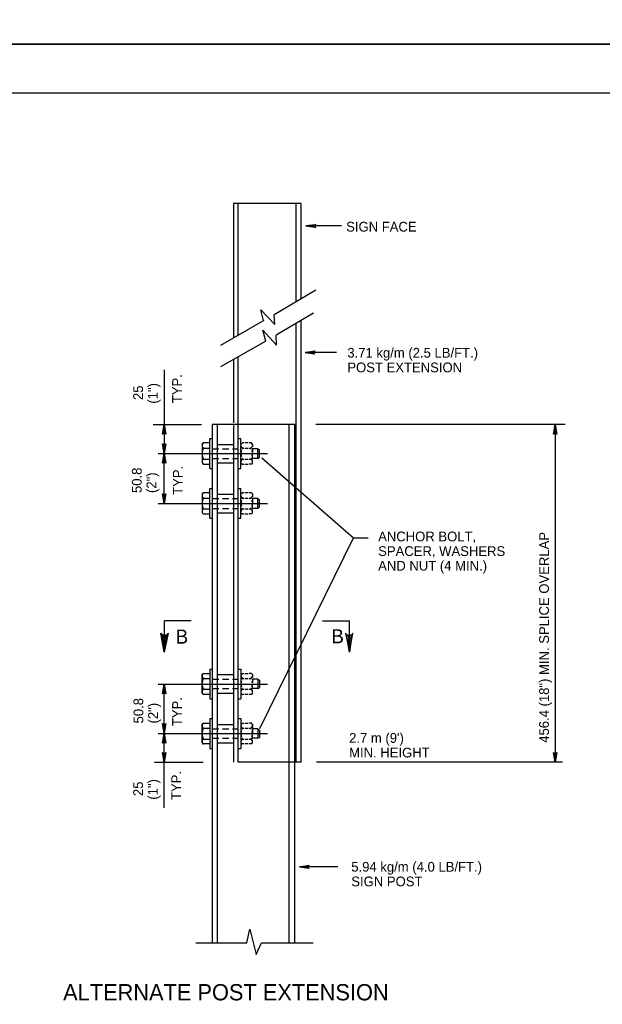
# Model space of a CAD drawing. Extents: x 644358 to 648627, y 294594 to 295782.
# Drawn here: x 644576.7 to 644755.6, y 294892.7 to 295195.1 of the extents above; entities that cross this region are included whole.
import ezdxf

# ---------------------------------------------------------------- set-up
doc = ezdxf.new("R2010")
doc.units = 0
for name, color, linetype in [('1', 7, 'Continuous'), ('2', 7, 'Continuous'), ('3', 7, 'Continuous'), ('4', 7, 'Continuous'), ('PLT-BNDY', 7, 'Continuous')]:
    doc.layers.add(name, color=color, linetype=linetype)

# ---------------------------------------------------------------- blocks, each defined once
blk = doc.blocks.new('RARROW')
at = {"layer": '3'}
blk.add_lwpolyline([(-2.2695, 0.285), (-2.184875, 0.12075), (0, 0), (-2.2695, 0.285), (-2.38575, 0.384625), (0, 0), (-2.183125, -0.108), (-2.262875, -0.2705), (0, 0), (-2.38575, -0.379125), (-2.262875, -0.2705)], dxfattribs=at)

msp = doc.modelspace()

# ---------------------------------------------------------------- linework, layer by layer
at = {"layer": '1'}
for p, q in [((644398.31, 295172.63), (645184.31, 295172.63)), ((644648.21, 295064.63), (644648.21, 295063.88)), ((644648.21, 295063.51), (644648.21, 295062.13)), ((644648.21, 295060.26), (644648.21, 295061.51)), ((644648.21, 295059.01), (644648.21, 295060.01)), ((644648.21, 295049.51), (644648.21, 295048.51)), ((644648.21, 295048.13), (644648.21, 295046.76)), ((644648.21, 295045.01), (644648.21, 295046.26)), ((644648.21, 295043.63), (644648.21, 295044.63)), ((644648.21, 294994.01), (644648.21, 294993.01)), ((644648.21, 294992.63), (644648.21, 294991.38)), ((644648.21, 294989.51), (644648.21, 294990.88)), ((644648.21, 294988.26), (644648.21, 294989.13)), ((644648.21, 294978.63), (644648.21, 294977.63)), ((644648.21, 294977.38), (644648.21, 294976.01)), ((644648.21, 294974.13), (644648.21, 294975.51)), ((644648.21, 294973.01), (644648.21, 294973.76))]:
    msp.add_line(p, q, dxfattribs=at)
for points in [[(644622.09, 295006.26), (644621.46, 295006.01), (644621.09, 295000.88), (644622.09, 295006.26), (644622.34, 295006.63), (644621.09, 295000.88), (644620.96, 295006.01), (644620.46, 295006.26), (644621.09, 295000.88), (644620.09, 295006.63), (644620.46, 295006.26)], [(644677.09, 295006.26), (644677.59, 295006.01), (644677.96, 295000.88), (644677.09, 295006.26), (644676.71, 295006.63), (644677.96, 295000.88), (644678.21, 295006.01), (644678.71, 295006.26), (644677.96, 295000.88), (644678.96, 295006.63), (644678.71, 295006.26)]]:
    msp.add_lwpolyline(points, dxfattribs=at)
for centre, radius, start, end in [((644645.47, 295064.34), 0.81, 184.8919, 254.2247), ((644647.69, 295061.85), 3.04, 146.6027, 154.678), ((644647.35, 295064.34), 0.81, 285.7753, 351.6558), ((644645.13, 295061.85), 3.04, 24.9174, 33.3973), ((644647.69, 295061.85), 3.04, 162.8799, 197.6126), ((644645.47, 295059.39), 0.81, 106.5107, 186.623), ((644647.69, 295061.85), 3.04, 205.6812, 213.3973), ((644647.35, 295059.39), 0.81, 358.7185, 73.4893), ((644645.13, 295061.85), 3.04, 326.6027, 334.9746), ((644645.13, 295061.85), 3.04, 6.0459, 16.9125), ((644645.13, 295061.85), 3.04, 344.0189, 354.4846), ((644645.47, 295049.01), 0.81, 184.8919, 254.2247), ((644647.69, 295046.52), 3.04, 146.6027, 154.678), ((644647.35, 295049.01), 0.81, 285.7753, 351.6558), ((644645.13, 295046.52), 3.04, 24.9174, 33.3973), ((644647.69, 295046.52), 3.04, 162.8799, 197.6126), ((644645.47, 295044.05), 0.81, 106.5107, 186.623), ((644647.69, 295046.52), 3.04, 205.6812, 213.3973), ((644647.35, 295044.05), 0.81, 358.7185, 73.4893), ((644645.13, 295046.52), 3.04, 326.6027, 334.9746), ((644645.13, 295046.52), 3.04, 6.0459, 16.9125), ((644645.13, 295046.52), 3.04, 344.0189, 354.4846), ((644645.47, 294993.59), 0.81, 173.377, 253.4893), ((644647.35, 294993.59), 0.81, 286.5107, 1.2815), ((644647.69, 294991.13), 3.04, 162.3874, 197.1201), ((644647.69, 294991.13), 3.04, 146.6027, 154.3188), ((644645.13, 294991.13), 3.04, 25.0254, 33.3973), ((644645.13, 294991.13), 3.04, 343.0875, 353.9541), ((644645.13, 294991.13), 3.04, 5.5154, 15.9811), ((644645.47, 294988.64), 0.81, 105.7753, 175.1081), ((644647.69, 294991.13), 3.04, 205.322, 213.3973), ((644647.35, 294988.64), 0.81, 8.3442, 74.2247), ((644645.13, 294991.13), 3.04, 326.6027, 335.0826), ((644645.47, 294978.26), 0.81, 173.377, 253.4893), ((644647.35, 294978.26), 0.81, 286.5107, 1.2815), ((644647.69, 294975.8), 3.04, 162.3874, 197.1201), ((644647.69, 294975.8), 3.04, 146.6027, 154.3188), ((644645.13, 294975.8), 3.04, 25.0254, 33.3973), ((644645.13, 294975.8), 3.04, 343.0875, 353.9541), ((644645.13, 294975.8), 3.04, 5.5154, 15.9811), ((644645.47, 294973.3), 0.81, 105.7753, 175.1081), ((644647.69, 294975.8), 3.04, 205.322, 213.3973), ((644647.35, 294973.3), 0.81, 8.3442, 74.2247), ((644645.13, 294975.8), 3.04, 326.6027, 335.0826)]:
    msp.add_arc(centre, radius, start, end, dxfattribs=at)
for centre, major_axis, start_param, end_param in [((644635.44, 295061.85), (0, -3.04), 4.129496, 5.295282), ((644633.44, 295064.34), (0, 0.81), 0.448108, 2.866262), ((644633.44, 295059.39), (0, -0.81), 3.429758, 5.835077), ((644635.44, 295046.52), (0, -3.04), 4.129496, 5.295282), ((644633.44, 295049.01), (0, 0.81), 0.448108, 2.866262), ((644633.44, 295044.05), (0, -0.81), 3.429758, 5.835077), ((644633.44, 294993.59), (0, 0.81), 0.448108, 2.853427), ((644635.44, 294991.13), (0, 3.04), 0.987904, 2.153689), ((644633.44, 294988.64), (0, -0.81), 3.416923, 5.835077), ((644633.44, 294978.26), (0, 0.81), 0.448108, 2.853427), ((644635.44, 294975.8), (0, 3.04), 0.987904, 2.153689), ((644633.44, 294973.3), (0, -0.81), 3.416923, 5.835077)]:
    msp.add_ellipse(centre, major_axis=major_axis, ratio=0.9, start_param=start_param, end_param=end_param, dxfattribs=at)
at = {"layer": '2'}
for p, q in [((644663.09, 295138.63), (644642.34, 295138.63)), ((644642.34, 295138.63), (644642.34, 295097.38)), ((644643.84, 295098.26), (644643.84, 295138.63)), ((644661.59, 295108.38), (644661.59, 295138.88)), ((644663.09, 295109.38), (644663.09, 295138.63)), ((644667.59, 295112.01), (644654.84, 295104.51)), ((644651.71, 295102.76), (644638.34, 295095.01)), ((644666.96, 295105.01), (644655.46, 295098.26)), ((644663.09, 294967.01), (644663.09, 295102.76)), ((644661.59, 294967.01), (644661.59, 295101.88)), ((644652.34, 295096.38), (644638.34, 295088.51)), ((644642.34, 295090.76), (644642.34, 295071.26)), ((644643.84, 294967.01), (644643.84, 295091.51)), ((644661.21, 295070.76), (644635.84, 295070.76)), ((644635.84, 295070.76), (644635.84, 294911.51)), ((644637.34, 295070.76), (644637.34, 294911.51)), ((644642.34, 295070.51), (644642.34, 294967.01)), ((644659.46, 294911.51), (644659.46, 295070.76)), ((644661.21, 294911.51), (644661.21, 295070.76)), ((644635.09, 295066.51), (644635.84, 295066.51)), ((644635.09, 295057.26), (644635.09, 295066.51)), ((644643.84, 295066.51), (644644.59, 295066.51)), ((644644.59, 295057.26), (644644.59, 295066.51)), ((644632.71, 295064.63), (644633.09, 295065.13)), ((644632.71, 295064.63), (644632.71, 295059.01)), ((644635.09, 295065.13), (644633.09, 295065.13)), ((644633.21, 295063.51), (644635.09, 295063.51)), ((644635.84, 295063.26), (644637.84, 295063.26)), ((644637.34, 295064.63), (644642.34, 295064.63)), ((644638.96, 295063.26), (644640.96, 295063.26)), ((644642.09, 295063.26), (644643.84, 295063.26)), ((644644.59, 295064.63), (644645.09, 295065.13)), ((644645.59, 295065.13), (644645.09, 295065.13)), ((644645.21, 295063.51), (644645.59, 295063.51)), ((644646.84, 295065.13), (644645.96, 295065.13)), ((644645.96, 295063.51), (644646.84, 295063.51)), ((644647.84, 295065.13), (644647.21, 295065.13)), ((644647.21, 295063.51), (644647.71, 295063.51)), ((644648.21, 295064.63), (644647.84, 295065.13)), ((644649.84, 295063.26), (644648.21, 295063.26)), ((644649.84, 295060.38), (644649.84, 295063.26)), ((644649.84, 295063.26), (644650.34, 295063.01)), ((644650.34, 295060.76), (644650.34, 295063.01)), ((644633.21, 295060.13), (644635.09, 295060.13)), ((644635.84, 295060.38), (644637.84, 295060.38)), ((644638.96, 295060.38), (644640.96, 295060.38)), ((644642.09, 295060.38), (644643.84, 295060.38)), ((644645.21, 295060.13), (644645.59, 295060.13)), ((644645.96, 295060.13), (644646.84, 295060.13)), ((644647.21, 295060.13), (644647.71, 295060.13)), ((644649.84, 295060.38), (644648.21, 295060.38)), ((644649.84, 295060.38), (644650.34, 295060.76)), ((644632.71, 295059.01), (644633.09, 295058.63)), ((644633.09, 295058.63), (644635.09, 295058.63)), ((644635.09, 295057.26), (644635.84, 295057.26)), ((644637.34, 295059.01), (644642.34, 295059.01)), ((644643.84, 295057.26), (644644.59, 295057.26)), ((644644.59, 295059.01), (644645.09, 295058.63)), ((644645.09, 295058.63), (644645.59, 295058.63)), ((644645.96, 295058.63), (644646.84, 295058.63)), ((644647.84, 295058.63), (644647.21, 295058.63)), ((644648.21, 295059.01), (644647.84, 295058.63)), ((644635.09, 295051.13), (644635.84, 295051.13)), ((644635.09, 295042.01), (644635.09, 295051.13)), ((644643.84, 295051.13), (644644.59, 295051.13)), ((644644.59, 295042.01), (644644.59, 295051.13)), ((644632.71, 295049.51), (644633.09, 295049.76)), ((644632.71, 295049.51), (644632.71, 295043.63)), ((644635.09, 295049.76), (644633.09, 295049.76)), ((644633.21, 295048.13), (644635.09, 295048.13)), ((644635.84, 295048.01), (644637.84, 295048.01)), ((644637.34, 295049.38), (644642.34, 295049.38)), ((644638.96, 295048.01), (644640.96, 295048.01)), ((644642.09, 295048.01), (644643.84, 295048.01)), ((644644.59, 295049.51), (644645.09, 295049.76)), ((644645.59, 295049.76), (644645.09, 295049.76)), ((644645.21, 295048.13), (644645.59, 295048.13)), ((644646.84, 295049.76), (644645.96, 295049.76)), ((644645.96, 295048.13), (644646.84, 295048.13)), ((644647.84, 295049.76), (644647.21, 295049.76)), ((644647.21, 295048.13), (644647.71, 295048.13)), ((644648.21, 295049.51), (644647.84, 295049.76)), ((644649.84, 295048.01), (644648.21, 295048.01)), ((644649.84, 295045.01), (644649.84, 295048.01)), ((644649.84, 295048.01), (644650.34, 295047.63)), ((644633.21, 295044.88), (644635.09, 295044.88)), ((644635.84, 295045.01), (644637.84, 295045.01)), ((644638.96, 295045.01), (644640.96, 295045.01)), ((644642.09, 295045.01), (644643.84, 295045.01)), ((644645.21, 295044.88), (644645.59, 295044.88)), ((644645.96, 295044.88), (644646.84, 295044.88)), ((644647.21, 295044.88), (644647.71, 295044.88)), ((644649.84, 295045.01), (644648.21, 295045.01)), ((644649.84, 295045.01), (644650.34, 295045.51)), ((644650.34, 295045.51), (644650.34, 295047.63)), ((644632.71, 295043.63), (644633.09, 295043.38)), ((644633.09, 295043.38), (644635.09, 295043.38)), ((644635.09, 295042.01), (644635.84, 295042.01)), ((644637.34, 295043.63), (644642.34, 295043.63)), ((644643.84, 295042.01), (644644.59, 295042.01)), ((644644.59, 295043.63), (644645.09, 295043.38)), ((644645.09, 295043.38), (644645.59, 295043.38)), ((644645.96, 295043.38), (644646.84, 295043.38)), ((644647.84, 295043.38), (644647.21, 295043.38)), ((644648.21, 295043.63), (644647.84, 295043.38)), ((644629.34, 295010.51), (644621.21, 295010.51)), ((644621.21, 295003.76), (644621.21, 295010.51)), ((644669.71, 295010.51), (644677.96, 295010.51)), ((644677.96, 295003.76), (644677.96, 295010.51)), ((644632.71, 294994.01), (644633.09, 294994.26)), ((644632.71, 294988.26), (644632.71, 294994.01)), ((644633.09, 294994.26), (644635.09, 294994.26)), ((644635.09, 294995.63), (644635.84, 294995.63)), ((644635.09, 294995.63), (644635.09, 294986.51)), ((644637.34, 294994.01), (644642.34, 294994.01)), ((644643.84, 294995.63), (644644.59, 294995.63)), ((644644.59, 294995.63), (644644.59, 294986.51)), ((644644.59, 294994.01), (644645.09, 294994.26)), ((644645.09, 294994.26), (644645.59, 294994.26)), ((644645.96, 294994.26), (644646.84, 294994.26)), ((644647.84, 294994.26), (644647.21, 294994.26)), ((644648.21, 294994.01), (644647.84, 294994.26)), ((644633.21, 294992.76), (644635.09, 294992.76)), ((644635.84, 294992.51), (644637.84, 294992.51)), ((644638.96, 294992.51), (644640.96, 294992.51)), ((644642.09, 294992.51), (644643.84, 294992.51)), ((644645.21, 294992.76), (644645.59, 294992.76)), ((644645.96, 294992.76), (644646.84, 294992.76)), ((644647.21, 294992.76), (644647.71, 294992.76)), ((644649.84, 294992.51), (644648.21, 294992.51)), ((644649.84, 294992.51), (644649.84, 294989.63)), ((644649.84, 294992.51), (644650.34, 294992.26)), ((644650.34, 294992.26), (644650.34, 294990.01)), ((644632.71, 294988.26), (644633.09, 294987.88)), ((644635.09, 294987.88), (644633.09, 294987.88)), ((644633.21, 294989.51), (644635.09, 294989.51)), ((644635.84, 294989.63), (644637.84, 294989.63)), ((644637.34, 294988.26), (644642.34, 294988.26)), ((644638.96, 294989.63), (644640.96, 294989.63)), ((644642.09, 294989.63), (644643.84, 294989.63)), ((644644.59, 294988.26), (644645.09, 294987.88)), ((644645.59, 294987.88), (644645.09, 294987.88)), ((644645.21, 294989.51), (644645.59, 294989.51)), ((644645.96, 294989.51), (644646.84, 294989.51)), ((644646.84, 294987.88), (644645.96, 294987.88)), ((644647.21, 294989.51), (644647.71, 294989.51)), ((644647.84, 294987.88), (644647.21, 294987.88)), ((644648.21, 294988.26), (644647.84, 294987.88)), ((644649.84, 294989.63), (644648.21, 294989.63)), ((644649.84, 294989.63), (644650.34, 294990.01)), ((644635.09, 294986.51), (644635.84, 294986.51)), ((644643.84, 294986.51), (644644.59, 294986.51)), ((644632.71, 294978.63), (644633.09, 294979.01)), ((644632.71, 294973.01), (644632.71, 294978.63)), ((644633.09, 294979.01), (644635.09, 294979.01)), ((644635.09, 294980.51), (644635.84, 294980.51)), ((644635.09, 294980.51), (644635.09, 294971.26)), ((644637.34, 294978.63), (644642.34, 294978.63)), ((644643.84, 294980.51), (644644.59, 294980.51)), ((644644.59, 294980.51), (644644.59, 294971.26)), ((644644.59, 294978.63), (644645.09, 294979.01)), ((644645.09, 294979.01), (644645.59, 294979.01)), ((644645.96, 294979.01), (644646.84, 294979.01)), ((644647.84, 294979.01), (644647.21, 294979.01)), ((644648.21, 294978.63), (644647.84, 294979.01)), ((644633.21, 294977.51), (644635.09, 294977.51)), ((644635.84, 294977.26), (644637.84, 294977.26)), ((644638.96, 294977.26), (644640.96, 294977.26)), ((644642.09, 294977.26), (644643.84, 294977.26)), ((644645.21, 294977.51), (644645.59, 294977.51)), ((644645.96, 294977.51), (644646.84, 294977.51)), ((644647.21, 294977.51), (644647.71, 294977.51)), ((644649.84, 294977.26), (644648.21, 294977.26)), ((644649.84, 294977.26), (644649.84, 294974.38)), ((644649.84, 294977.26), (644650.34, 294976.88)), ((644650.34, 294976.88), (644650.34, 294974.63)), ((644632.71, 294973.01), (644633.09, 294972.63)), ((644635.09, 294972.63), (644633.09, 294972.63)), ((644633.21, 294974.13), (644635.09, 294974.13)), ((644635.84, 294974.38), (644637.84, 294974.38)), ((644637.34, 294973.01), (644642.34, 294973.01)), ((644638.96, 294974.38), (644640.96, 294974.38)), ((644642.09, 294974.38), (644643.84, 294974.38)), ((644644.59, 294973.01), (644645.09, 294972.63)), ((644645.59, 294972.63), (644645.09, 294972.63)), ((644645.21, 294974.13), (644645.59, 294974.13)), ((644645.96, 294974.13), (644646.84, 294974.13)), ((644646.84, 294972.63), (644645.96, 294972.63)), ((644647.21, 294974.13), (644647.71, 294974.13)), ((644647.84, 294972.63), (644647.21, 294972.63)), ((644648.21, 294973.01), (644647.84, 294972.63)), ((644649.84, 294974.38), (644648.21, 294974.38)), ((644649.84, 294974.38), (644650.34, 294974.63)), ((644635.09, 294971.26), (644635.84, 294971.26)), ((644643.84, 294971.26), (644644.59, 294971.26)), ((644663.09, 294967.01), (644643.84, 294967.01)), ((644630.84, 294911.51), (644646.46, 294911.51)), ((644650.96, 294911.51), (644666.84, 294911.51))]:
    msp.add_line(p, q, dxfattribs=at)
for points in [[(644651.59, 295102.76), (644650.71, 295106.01), (644655.09, 295101.51), (644654.84, 295104.51)], [(644651.59, 295102.76), (644650.71, 295106.01), (644655.09, 295101.51), (644654.84, 295104.51)], [(644652.34, 295096.38), (644651.34, 295099.76), (644655.59, 295095.13), (644655.46, 295098.26)], [(644652.34, 295096.38), (644651.34, 295099.76), (644655.59, 295095.13), (644655.46, 295098.26)], [(644646.46, 294911.51), (644647.34, 294915.76), (644649.34, 294908.01), (644650.96, 294911.51)]]:
    msp.add_lwpolyline(points, dxfattribs=at)
at = {"layer": '4'}
for p, q in [((644675.54, 295131.76), (644664.59, 295131.76)), ((644674.01, 295092.88), (644664.34, 295092.88)), ((644621.09, 295087.58), (644621.09, 295061.88)), ((644617.71, 295070.76), (644632.59, 295070.76)), ((644744.21, 295070.76), (644667.59, 295070.76)), ((644741.09, 295070.76), (644741.09, 294967.01)), ((644619.21, 295061.88), (644652.84, 295061.88)), ((644621.09, 295046.51), (644621.09, 295061.88)), ((644651.09, 295060.51), (644679.21, 295036.01)), ((644619.21, 295046.51), (644652.84, 295046.51)), ((644650.46, 294977.38), (644679.21, 295036.01)), ((644679.21, 295036.01), (644683.75, 295036.01)), ((644619.21, 294991.01), (644652.84, 294991.01)), ((644621.09, 294975.88), (644621.09, 294991.01)), ((644619.21, 294975.88), (644652.84, 294975.88)), ((644621.09, 294953.05), (644621.09, 294975.88)), ((644618.09, 294967.01), (644633.09, 294967.01)), ((644743.34, 294967.01), (644667.84, 294967.01)), ((644674.39, 294934.88), (644662.59, 294934.88))]:
    msp.add_line(p, q, dxfattribs=at)
at = {"layer": 'PLT-BNDY'}
for points in [[(644358.31, 295781.63), (645199.31, 295781.63), (645199.31, 295187.63), (644358.31, 295187.63)], [(644358.31, 295187.63), (645199.31, 295187.63), (645199.31, 294593.63), (644358.31, 294593.63)]]:
    msp.add_lwpolyline(points, close=True, dxfattribs=at)

# ---------------------------------------------------------------- block references
at = {"layer": '2', "xscale": 1.2574347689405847, "yscale": 1.3092961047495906}
for p, rotation in [((644664.59, 295131.76), 180), ((644664.34, 295092.88), 180), ((644621.09, 295070.76), 89.99999999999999), ((644741.09, 295070.76), 89.99999999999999), ((644621.09, 295061.88), -90.00000000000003), ((644621.09, 295061.88), 89.99999999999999), ((644621.09, 295046.51), -90.00000000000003), ((644621.09, 294991.01), 89.99999999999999), ((644621.09, 294975.88), -90.00000000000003), ((644621.09, 294975.88), 89.99999999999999), ((644621.09, 294967.01), -90.00000000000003), ((644741.09, 294967.01), -90.00000000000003), ((644662.59, 294934.88), 180)]:
    msp.add_blockref('RARROW', p, dxfattribs=dict(at, rotation=rotation))

# ---------------------------------------------------------------- texts
at = {"layer": '2'}
msp.add_text('ALTERNATE POST EXTENSION', height=5, dxfattribs=at).set_placement((644590.06, 294893.87))
at = {"layer": '4'}
for s, height, p in [(' SIGN FACE', 3, (644675.84, 295130.04)), ('3.71 kg/m (2.5 LB/FT.)', 3, (644677.31, 295091.31)), ('POST EXTENSION', 3, (644677.31, 295086.81)), ('ANCHOR BOLT,', 3, (644686.77, 295034.88)), ('SPACER, WASHERS', 3, (644686.77, 295030.38)), ('AND NUT (4 MIN.)', 3, (644686.77, 295025.88)), ('B', 4.3, (644624.6, 295003.47)), ('B', 4.3, (644672.42, 295003.57)), ("2.7 m (9') ", 3, (644677.85, 294973)), ('MIN. HEIGHT', 3, (644677.85, 294968.5)), ('5.94 kg/m (4.0 LB/FT.)', 3, (644678.52, 294933.41)), ('SIGN POST ', 3, (644678.52, 294928.91))]:
    msp.add_text(s, height=height, dxfattribs=at).set_placement(p)
for s, p in [('TYP.', (644626.53, 295077.33)), (' 25', (644614.58, 295077.17)), ('(1")', (644619.08, 295077.17)), ('50.8', (644614.17, 295049.73)), ('TYP.', (644626.78, 295049.16)), ('(2") ', (644618.67, 295049.73)), ('456.4 (18") MIN. SPLICE OVERLAP', (644739.2, 294973.01)), ('50.8', (644614.67, 294978.94)), ('(2") ', (644619.17, 294978.94)), ('TYP.', (644626.53, 294978.12)), ('TYP.', (644626.28, 294955.43)), (' 25', (644614.58, 294955.52)), ('(1")', (644619.08, 294955.52))]:
    msp.add_text(s, height=3, rotation=90, dxfattribs=at).set_placement(p)

doc.saveas('drawing.dxf')
